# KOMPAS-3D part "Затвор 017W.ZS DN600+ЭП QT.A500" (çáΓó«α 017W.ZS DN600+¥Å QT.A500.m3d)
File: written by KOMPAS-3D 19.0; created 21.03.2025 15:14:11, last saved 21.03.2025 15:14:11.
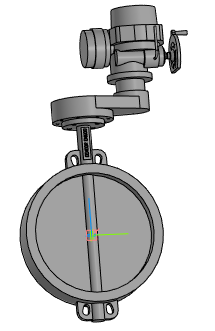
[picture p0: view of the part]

Document properties: Полное имя файла: Затвор 017W.ZS DN600+ЭП QT.A500.a3d

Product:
- Part/product: Затвор 017W.ZS DN600+ЭП QT.A500
    Масса: 430.487

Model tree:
1. Операция без истории:1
